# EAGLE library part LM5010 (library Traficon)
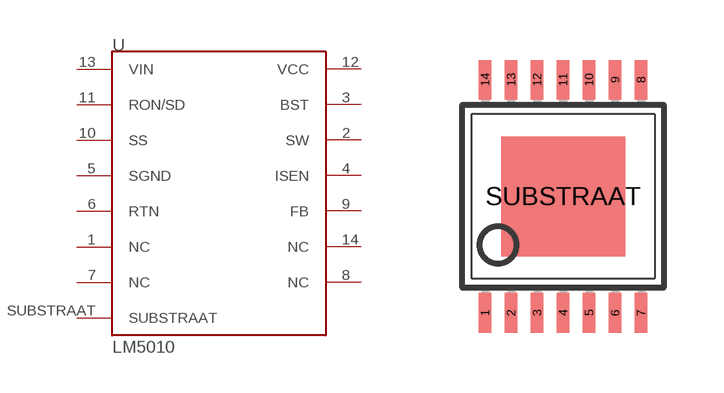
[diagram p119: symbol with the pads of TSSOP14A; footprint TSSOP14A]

Designator prefix U

## LM5010  [TSSOP14A]
1  NC
2  SW
3  BST
4  ISEN
5  SGND
6  RTN
7  NC
8  NC
9  FB
10  SS
11  RON/SD
12  VCC
13  VIN
14  NC
SUBSTRAAT  SUBSTRAAT  pas

## Footprint TSSOP14A (pad centres in mm)
smd 0.305 x 0.991: 1 -1.95,-2.918; 2 -1.3,-2.918; 3 -0.65,-2.918; 4 0,-2.918; 5 0.65,-2.918; 6 1.3,-2.918; 7 1.95,-2.918; 8 1.95,2.918; 9 1.3,2.918; 10 0.65,2.918; 11 0,2.918; 12 -0.65,2.918; 13 -1.3,2.918; 14 -1.95,2.918
smd 3.1 x 3: SUBSTRAAT 0,0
